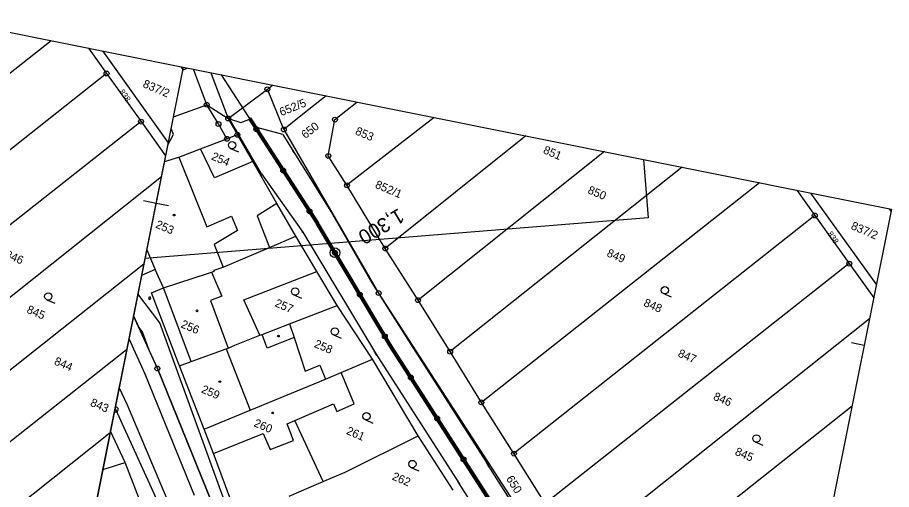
# Model space of a CAD drawing. Extents: x -548552 to -543113, y -1131925 to -1123599.
# Drawn here: x -548096.2 to -547916.5, y -1130558.1 to -1130461.1 of the extents above; entities that cross this region are included whole.
import ezdxf

# ---------------------------------------------------------------- set-up
doc = ezdxf.new("R2010")
doc.units = 0
for name, color, linetype in [('Hranice parcel', 7, 'Continuous'), ('HRANY', 7, 'Continuous'), ('NADZEMNÍ VEDENÍ VN', 7, 'Continuous'), ('Parcelní čísla', 7, 'Continuous'), ('Profile', 7, 'Continuous'), ('PROFILY NÁVRH', 7, 'Continuous'), ('STANIČENÍ', 7, 'Continuous'), ('SVAHY', 7, 'Continuous'), ('Vnitřní kresba', 7, 'Continuous'), ('Věcná břemena k části', 7, 'Continuous'), ('Značky bodu BP', 7, 'Continuous'), ('Značky budov', 7, 'Continuous'), ('Značky kultur', 7, 'Continuous')]:
    doc.layers.add(name, color=color, linetype=linetype)

msp = doc.modelspace()

# ---------------------------------------------------------------- linework, layer by layer
at = {"layer": 'Hranice parcel'}
for p, q in [((-548089.31, -1130465.88), (-548146.48, -1130511.03)), ((-548081.64, -1130467.42), (-548077.93, -1130472.61)), ((-548078.8, -1130467.99), (-548065.27, -1130486.88)), ((-548062.67, -1130471.23), (-548062.25, -1130471.81)), ((-548057.34, -1130479.04), (-548060.05, -1130471.75)), ((-548077.93, -1130472.61), (-548139.78, -1130521.55)), ((-548077.93, -1130472.61), (-548070.84, -1130482.5)), ((-548044.87, -1130475.86), (-548043.84, -1130475)), ((-548052.92, -1130481.87), (-548044.87, -1130475.86)), ((-548041.48, -1130484.13), (-548044.87, -1130475.86)), ((-548070.84, -1130482.5), (-548133.39, -1130531.79)), ((-548070.84, -1130482.5), (-548065.8, -1130489.54)), ((-548052.92, -1130481.87), (-548051.03, -1130485.23)), ((-548010.59, -1130481.67), (-548028.51, -1130495.6)), ((-548058.6, -1130488.12), (-548053.18, -1130486.05)), ((-548051.03, -1130485.23), (-548053.18, -1130486.05)), ((-548047.88, -1130490.69), (-548051.03, -1130485.23)), ((-547991.72, -1130485.45), (-548020.62, -1130508.57)), ((-547975.58, -1130488.68), (-548013.9, -1130519.21)), ((-547959.6, -1130491.88), (-548007.3, -1130529.78)), ((-548066.66, -1130493.83), (-548127.07, -1130541.87)), ((-547943.71, -1130495.07), (-548000.88, -1130540.21)), ((-548020.62, -1130508.57), (-548028.51, -1130495.6)), ((-547936.04, -1130496.61), (-547932.33, -1130501.8)), ((-547933.19, -1130497.18), (-547919.67, -1130516.07)), ((-547917.06, -1130500.41), (-547916.65, -1130500.99)), ((-547932.33, -1130501.8), (-547994.18, -1130550.73)), ((-547932.33, -1130501.8), (-547925.24, -1130511.69)), ((-548034.69, -1130513.31), (-548039.01, -1130506.06)), ((-548069.67, -1130508.83), (-548067.91, -1130512.9)), ((-548013.9, -1130519.21), (-548020.62, -1130508.57)), ((-548070.27, -1130511.83), (-548121.42, -1130552.32)), ((-548066.22, -1130516.64), (-548067.91, -1130512.9)), ((-548030.55, -1130520.28), (-548034.69, -1130513.31)), ((-547925.24, -1130511.69), (-547987.79, -1130560.98)), ((-547925.24, -1130511.69), (-547920.2, -1130518.73)), ((-548040.34, -1130524.03), (-548030.55, -1130520.28)), ((-548023.26, -1130531.32), (-548030.55, -1130520.28)), ((-548007.3, -1130529.78), (-548013.9, -1130519.21)), ((-547921.06, -1130523.02), (-547981.46, -1130571.05)), ((-548073.8, -1130529.42), (-548117.06, -1130563.53)), ((-548000.88, -1130540.21), (-548007.3, -1130529.78)), ((-548057.85, -1130545.71), (-548062.91, -1130532.7)), ((-548029.69, -1130534.09), (-548023.26, -1130531.32)), ((-548013.84, -1130547.08), (-548023.26, -1130531.32)), ((-548032.93, -1130535.41), (-548029.69, -1130534.09)), ((-547994.18, -1130550.73), (-548000.88, -1130540.21)), ((-547924.67, -1130541.01), (-547975.81, -1130581.5)), ((-548077.22, -1130546.47), (-548114.44, -1130576.02)), ((-548074.14, -1130552.54), (-548077.15, -1130546.14)), ((-548006.7, -1130558.22), (-548013.84, -1130547.08)), ((-547987.79, -1130560.98), (-547994.18, -1130550.73)), ((-548068.96, -1130565.7), (-548074.14, -1130552.54))]:
    msp.add_line(p, q, dxfattribs=at)
for points in [[(-548062.27, -1130471.9), (-548061.28, -1130471.5)], [(-548056.51, -1130472.46), (-548052.92, -1130481.87)], [(-548032.8, -1130477.21), (-548037.63, -1130481.06), (-548041.48, -1130484.13)], [(-548064.2, -1130481.54), (-548057.34, -1130479.04)], [(-548053.18, -1130486.05), (-548054.93, -1130482.99), (-548057.34, -1130479.04)], [(-548028.51, -1130495.6), (-548032.34, -1130489.56), (-548030.98, -1130482.09), (-548026.45, -1130478.49)], [(-548041.48, -1130484.13), (-548021.99, -1130517.74), (-547985.78, -1130573.7), (-547978.62, -1130586.61), (-547973.44, -1130599.62), (-547973.28, -1130611.12), (-547973.7, -1130624.88), (-547977.7, -1130646.84), (-547981.33, -1130656.63), (-547987.88, -1130668.6)], [(-548066.03, -1130490.68), (-548063.04, -1130489.81), (-548058.6, -1130488.12)], [(-548047.88, -1130490.69), (-548055.75, -1130494.06), (-548058.6, -1130488.12)], [(-548039.01, -1130506.06), (-548042.9, -1130499.31), (-548047.88, -1130490.69)], [(-548066.22, -1130516.64), (-548056.99, -1130513.63), (-548056.35, -1130513.43), (-548055.77, -1130513.24), (-548055.84, -1130513.03), (-548053.97, -1130512.43), (-548044.45, -1130508.38), (-548039.01, -1130506.06)], [(-548067.91, -1130512.9), (-548070.73, -1130514.12)], [(-548046.39, -1130526.41), (-548049.72, -1130519.13), (-548034.69, -1130513.31)], [(-548062.91, -1130532.7), (-548063.21, -1130532), (-548068.69, -1130517.71), (-548066.22, -1130516.64)], [(-548039.34, -1130606.65), (-548051.27, -1130573.08), (-548067.49, -1130533.25), (-548072.39, -1130522.4)], [(-548046.39, -1130526.41), (-548045.97, -1130526.24), (-548040.34, -1130524.03)], [(-548040.34, -1130524.03), (-548039.33, -1130526.85), (-548037.13, -1130533.79), (-548034.11, -1130532.55), (-548032.93, -1130535.41)], [(-548062.91, -1130532.7), (-548060.51, -1130531.83), (-548053.32, -1130529.22), (-548052.96, -1130529.06), (-548051.57, -1130528.46), (-548046.39, -1130526.41)], [(-548033.4, -1130556.48), (-548039.24, -1130543.9), (-548031.3, -1130540.53), (-548030.57, -1130542.11), (-548027.05, -1130540.49), (-548029.69, -1130534.09)], [(-548057.85, -1130545.71), (-548048.41, -1130541.81), (-548032.93, -1130535.41)], [(-548024.97, -1130684.14), (-548037.35, -1130647.39), (-548054.37, -1130595.1), (-548067.35, -1130560.8), (-548076.02, -1130541.68), (-548076.18, -1130541.3)], [(-548049.72, -1130563.51), (-548050.99, -1130564), (-548055.97, -1130550.71), (-548057.85, -1130545.71)], [(-548033.4, -1130556.48), (-548033.23, -1130556.41), (-548028.88, -1130554.56), (-548013.84, -1130547.08)], [(-548078.73, -1130554.02), (-548074.14, -1130552.54)], [(-548040.37, -1130559.48), (-548036.3, -1130557.72), (-548033.4, -1130556.48)]]:
    msp.add_lwpolyline(points, dxfattribs=at)
at = {"layer": 'HRANY'}
for p in [(-548050.3, -1130482.67), (-548048.34, -1130481.73)]:
    msp.add_line(p, (-548048.71, -1130482.08), dxfattribs=at)
at = {"layer": 'NADZEMNÍ VEDENÍ VN'}
for p, q in [((-548048.34, -1130481.73), (-548047.04, -1130483.74)), ((-548023.38, -1130515.61), (-548016.57, -1130526.48))]:
    msp.add_line(p, q, dxfattribs=at)
at = {"layer": 'Profile'}
for p, q in [((-548113.13, -1130461.11), (-548062.15, -1130471.33)), ((-548062.15, -1130471.33), (-548080.98, -1130565.27)), ((-547967.53, -1130490.3), (-547916.55, -1130500.51)), ((-548067.76, -1130499.31), (-548070.35, -1130498.79)), ((-548065.17, -1130499.83), (-548067.76, -1130499.31)), ((-547916.55, -1130500.51), (-547935.38, -1130594.45)), ((-548070.04, -1130510.66), (-548104.09, -1130680.55)), ((-547922.16, -1130528.49), (-547924.75, -1130527.97))]:
    msp.add_line(p, q, dxfattribs=at)
at = {"layer": 'PROFILY NÁVRH'}
for p, q in [((-548054.37, -1130472.89), (-548034.58, -1130503.42)), ((-548046.09, -1130493.23), (-548052.65, -1130481.96)), ((-548052.65, -1130481.96), (-548050.3, -1130482.67)), ((-548048.71, -1130482.08), (-548034.79, -1130503.56)), ((-548048.34, -1130481.73), (-548034.37, -1130503.29)), ((-548041.72, -1130485.17), (-548047.04, -1130483.74)), ((-548041.72, -1130485.17), (-548031.45, -1130501.55)), ((-548046.09, -1130493.23), (-548037.61, -1130505.23)), ((-548031.45, -1130501.55), (-548023.38, -1130515.61)), ((-548037.61, -1130505.23), (-548022.65, -1130530.11)), ((-548016.57, -1130526.48), (-547999.5, -1130553.08)), ((-548022.65, -1130530.11), (-548005.43, -1130556.89)), ((-547985.25, -1130575.52), (-547999.5, -1130553.08))]:
    msp.add_line(p, q, dxfattribs=at)
for points in [[(-547988.62, -1130577.15), (-548019.63, -1130528.94), (-548034.8, -1130503.55)], [(-547988.2, -1130576.88), (-548019.2, -1130528.68), (-548034.37, -1130503.29)], [(-547991.16, -1130579.07), (-548005.43, -1130556.89)]]:
    msp.add_lwpolyline(points, dxfattribs=at)
at = {"layer": 'STANIČENÍ'}
for points in [[(-548039.39, -1130488.85), (-548039.69, -1130488.43)], [(-548045.9, -1130493.49), (-548046.21, -1130493.06)], [(-548031.41, -1130501.62), (-548031.5, -1130501.46)], [(-547988.41, -1130577.01), (-548019.42, -1130528.81), (-548034.58, -1130503.42)], [(-548037.55, -1130505.32), (-548037.7, -1130505.11)], [(-548022.34, -1130530.63), (-548022.34, -1130530.62), (-548022.89, -1130529.7)], [(-547999.31, -1130553.38), (-547999.84, -1130552.56)], [(-548005.17, -1130557.3), (-548005.73, -1130556.42)]]:
    msp.add_lwpolyline(points, dxfattribs=at)
for centre, radius in [((-548048.2, -1130482.41), 0.1), ((-548047.68, -1130483.21), 0.1), ((-548047.13, -1130484.06), 0.5), ((-548047.13, -1130484.06), 0.1), ((-548046.53, -1130484.99), 0.1), ((-548045.98, -1130485.83), 0.1), ((-548045.44, -1130486.67), 0.1), ((-548044.9, -1130487.51), 0.1), ((-548044.35, -1130488.35), 0.1), ((-548043.81, -1130489.18), 0.1), ((-548043.26, -1130490.02), 0.1), ((-548042.72, -1130490.86), 0.1), ((-548042.18, -1130491.7), 0.1), ((-548041.63, -1130492.54), 0.5), ((-548041.63, -1130492.54), 0.1), ((-548041.09, -1130493.38), 0.1), ((-548040.55, -1130494.22), 0.1), ((-548040, -1130495.06), 0.1), ((-548039.46, -1130495.9), 0.1), ((-548038.91, -1130496.74), 0.1), ((-548038.37, -1130497.58), 0.1), ((-548037.83, -1130498.42), 0.1), ((-548037.28, -1130499.26), 0.1), ((-548036.74, -1130500.09), 0.1), ((-548036.2, -1130500.93), 0.5), ((-548036.2, -1130500.93), 0.1), ((-548035.65, -1130501.77), 0.1), ((-548035.11, -1130502.61), 0.1), ((-548034.56, -1130503.45), 0.1), ((-548034.05, -1130504.31), 0.1), ((-548033.54, -1130505.17), 0.1), ((-548033.03, -1130506.03), 0.1), ((-548032.51, -1130506.89), 0.1), ((-548032, -1130507.74), 0.1), ((-548032, -1130507.74), 0.1), ((-548030.97, -1130509.46), 1), ((-548031.49, -1130508.6), 0.1), ((-548031.49, -1130508.6), 0.1), ((-548030.97, -1130509.46), 0.5), ((-548030.97, -1130509.46), 0.5), ((-548030.97, -1130509.46), 0.1), ((-548030.97, -1130509.46), 0.1), ((-548030.46, -1130510.32), 0.1), ((-548030.46, -1130510.32), 0.1), ((-548029.95, -1130511.18), 0.1), ((-548029.95, -1130511.18), 0.1), ((-548029.44, -1130512.04), 0.1), ((-548029.44, -1130512.04), 0.1), ((-548028.92, -1130512.89), 0.1), ((-548028.92, -1130512.89), 0.1), ((-548028.41, -1130513.75), 0.1), ((-548027.9, -1130514.61), 0.1), ((-548027.38, -1130515.47), 0.1), ((-548026.87, -1130516.33), 0.1), ((-548026.36, -1130517.19), 0.1), ((-548025.85, -1130518.05), 0.5), ((-548025.85, -1130518.05), 0.1), ((-548025.33, -1130518.9), 0.1), ((-548024.82, -1130519.76), 0.1), ((-548024.31, -1130520.62), 0.1), ((-548023.79, -1130521.48), 0.1), ((-548023.28, -1130522.34), 0.1), ((-548022.77, -1130523.2), 0.1), ((-548022.26, -1130524.06), 0.1), ((-548021.74, -1130524.91), 0.1), ((-548021.23, -1130525.77), 0.1), ((-548020.72, -1130526.63), 0.5), ((-548020.72, -1130526.63), 0.1), ((-548020.2, -1130527.49), 0.1), ((-548019.69, -1130528.35), 0.1), ((-548019.17, -1130529.2), 0.1), ((-548018.62, -1130530.04), 0.1), ((-548018.08, -1130530.88), 0.1), ((-548017.54, -1130531.72), 0.1), ((-548017, -1130532.56), 0.1), ((-548016.46, -1130533.4), 0.1), ((-548015.92, -1130534.24), 0.1), ((-548015.38, -1130535.08), 0.5), ((-548015.38, -1130535.08), 0.1), ((-548014.84, -1130535.93), 0.1), ((-548014.3, -1130536.77), 0.1), ((-548013.76, -1130537.61), 0.1), ((-548013.21, -1130538.45), 0.1), ((-548012.67, -1130539.29), 0.1), ((-548012.13, -1130540.13), 0.1), ((-548011.59, -1130540.97), 0.1), ((-548011.05, -1130541.81), 0.1), ((-548010.51, -1130542.65), 0.1), ((-548009.97, -1130543.5), 0.5), ((-548009.97, -1130543.5), 0.1), ((-548009.43, -1130544.34), 0.1), ((-548008.89, -1130545.18), 0.1), ((-548008.35, -1130546.02), 0.1), ((-548007.81, -1130546.86), 0.1), ((-548007.26, -1130547.7), 0.1), ((-548006.72, -1130548.54), 0.1), ((-548006.18, -1130549.38), 0.1), ((-548005.64, -1130550.22), 0.1), ((-548005.1, -1130551.06), 0.1), ((-548004.56, -1130551.91), 0.5), ((-548004.56, -1130551.91), 0.1), ((-548004.02, -1130552.75), 0.1), ((-548003.48, -1130553.59), 0.1), ((-548002.94, -1130554.43), 0.1), ((-548002.4, -1130555.27), 0.1), ((-548001.85, -1130556.11), 0.1), ((-548001.31, -1130556.95), 0.1), ((-548000.77, -1130557.79), 0.1)]:
    msp.add_circle(centre, radius, dxfattribs=at)
at = {"layer": 'SVAHY'}
for p, q in [((-548062.15, -1130471.33), (-548070.04, -1130510.66)), ((-548062.15, -1130471.33), (-547967.53, -1130490.3)), ((-547967.53, -1130490.3), (-547966.56, -1130502.27)), ((-547966.56, -1130502.27), (-548070.04, -1130510.66))]:
    msp.add_line(p, q, dxfattribs=at)
at = {"layer": 'Vnitřní kresba'}
for p, q in [((-548057.34, -1130479.04), (-548052.92, -1130481.87)), ((-548063.04, -1130489.81), (-548057.32, -1130504.11)), ((-548042.9, -1130499.31), (-548046.96, -1130501.85)), ((-548057.32, -1130504.11), (-548052.23, -1130501.94)), ((-548052.23, -1130501.94), (-548051.04, -1130504.85)), ((-548046.96, -1130501.85), (-548044.45, -1130508.38)), ((-548051.04, -1130504.85), (-548055.84, -1130507.79)), ((-548055.84, -1130507.79), (-548053.97, -1130512.43)), ((-548056.35, -1130513.43), (-548054.24, -1130518.36)), ((-548060.51, -1130531.83), (-548066.22, -1130516.64)), ((-548054.24, -1130518.36), (-548056.57, -1130519.25)), ((-548056.57, -1130519.25), (-548052.96, -1130529.06)), ((-548073.33, -1130527.06), (-548070.08, -1130534.37)), ((-548044.92, -1130529.06), (-548045.97, -1130526.24)), ((-548039.33, -1130526.85), (-548044.92, -1130529.06)), ((-548053.32, -1130529.22), (-548048.41, -1130541.81)), ((-548070.08, -1130534.37), (-548059.89, -1130559.25)), ((-548075.35, -1130537.18), (-548073.72, -1130540.69)), ((-548073.72, -1130540.69), (-548065.52, -1130560.02)), ((-548040.83, -1130544.58), (-548039.24, -1130543.9)), ((-548039.52, -1130548.05), (-548040.83, -1130544.58)), ((-548055.97, -1130550.71), (-548045.76, -1130546.57)), ((-548045.76, -1130546.57), (-548044.28, -1130549.86)), ((-548044.28, -1130549.86), (-548039.52, -1130548.05))]:
    msp.add_line(p, q, dxfattribs=at)
msp.add_lwpolyline([(-548065.33, -1130487.18), (-548065.24, -1130487.15), (-548064.19, -1130485.13), (-548064.68, -1130483.91)], dxfattribs=at)
at = {"layer": 'Věcná břemena k části'}
msp.add_line((-548071.5, -1130517.93), (-548072.39, -1130522.4), dxfattribs=at)
msp.add_lwpolyline([(-548072.39, -1130522.4), (-548071.31, -1130524.8), (-548070.52, -1130525.83), (-548069.21, -1130529.43), (-548067.49, -1130533.25), (-548051.27, -1130573.08), (-548039.34, -1130606.65), (-548038.34, -1130606.19), (-548037.86, -1130605.99), (-548037.61, -1130605.87), (-548046.61, -1130579.87), (-548066.97, -1130523.89), (-548071.5, -1130517.93)], dxfattribs=at)
msp.add_lwpolyline([(-548069.33, -1130518.68), (-548069.17, -1130519.06), (-548068.81, -1130518.9), (-548068.96, -1130518.54)], close=True, dxfattribs=at)
at = {"layer": 'Značky bodu BP'}
msp.add_line((-548076.16, -1130541.2), (-548076.33, -1130542.07), dxfattribs=at)
for centre, radius in [((-548077.93, -1130472.61), 0.5), ((-548077.93, -1130472.61), 0.0303), ((-548044.87, -1130475.86), 0.5), ((-548044.87, -1130475.86), 0.0303), ((-548057.34, -1130479.04), 0.5), ((-548057.34, -1130479.04), 0.0303), ((-548070.84, -1130482.5), 0.5), ((-548070.84, -1130482.5), 0.0303), ((-548054.93, -1130482.99), 0.5), ((-548052.92, -1130481.87), 0.5), ((-548052.92, -1130481.87), 0.0303), ((-548030.98, -1130482.09), 0.5), ((-548030.98, -1130482.09), 0.0303), ((-548054.93, -1130482.99), 0.0303), ((-548041.48, -1130484.13), 0.5), ((-548041.48, -1130484.13), 0.0303), ((-548053.18, -1130486.05), 0.5), ((-548053.18, -1130486.05), 0.0303), ((-548051.03, -1130485.23), 0.5), ((-548051.03, -1130485.23), 0.0303), ((-548032.34, -1130489.56), 0.5), ((-548032.34, -1130489.56), 0.0303), ((-548028.51, -1130495.6), 0.5), ((-548028.51, -1130495.6), 0.0303), ((-547932.33, -1130501.8), 0.5), ((-547932.33, -1130501.8), 0.0303), ((-548020.62, -1130508.57), 0.5), ((-548020.62, -1130508.57), 0.0303), ((-547925.24, -1130511.69), 0.5), ((-547925.24, -1130511.69), 0.0303), ((-548021.99, -1130517.74), 0.5), ((-548021.99, -1130517.74), 0.0303), ((-548013.9, -1130519.21), 0.5), ((-548013.9, -1130519.21), 0.0303), ((-548007.3, -1130529.78), 0.5), ((-548007.3, -1130529.78), 0.0303), ((-548067.49, -1130533.25), 0.5), ((-548067.49, -1130533.25), 0.0303), ((-548000.88, -1130540.21), 0.5), ((-548000.88, -1130540.21), 0.0303), ((-548076.02, -1130541.68), 0.0303), ((-547994.18, -1130550.73), 0.5), ((-547994.18, -1130550.73), 0.0303)]:
    msp.add_circle(centre, radius, dxfattribs=at)
msp.add_arc((-548076.02, -1130541.68), 0.5, 230.727, 106.6037, dxfattribs=at)
at = {"layer": 'Značky budov'}
for centre in [(-548064.05, -1130501.72), (-548059.35, -1130521.39), (-548042.59, -1130526.59), (-548054.64, -1130535.95), (-548043.78, -1130542.37)]:
    msp.add_circle(centre, 0.175, dxfattribs=at)
at = {"layer": 'Značky kultur'}
for p, q in [((-548052.43, -1130488.04), (-548050.82, -1130488.73)), ((-548039.44, -1130518.12), (-548037.84, -1130518.81)), ((-547963.45, -1130517.85), (-547961.84, -1130518.54)), ((-548090.21, -1130519.11), (-548088.6, -1130519.8)), ((-548031.29, -1130526.34), (-548029.69, -1130527.03)), ((-548024.79, -1130543.75), (-548023.18, -1130544.44)), ((-547944.61, -1130548.3), (-547943, -1130548.99)), ((-548015.36, -1130553.56), (-548013.75, -1130554.25))]:
    msp.add_line(p, q, dxfattribs=at)
for centre in [(-548052.13, -1130487.35), (-548039.15, -1130517.43), (-547963.15, -1130517.16), (-548089.91, -1130518.42), (-548031, -1130525.65), (-548024.49, -1130543.06), (-547944.31, -1130547.61), (-548015.06, -1130552.87)]:
    msp.add_circle(centre, 0.75, dxfattribs=at)

# ---------------------------------------------------------------- texts
at = {"layer": 'Parcelní čísla'}
for s, height, rotation, p in [('837/2', 1.7, 336.8058, (-548070.63, -1130475.35)), ('838', 1.2, 304.8058, (-548075.4, -1130476.37)), ('652/5', 1.7, 21.8058, (-548041.99, -1130481.41)), ('650', 1.7, 37.8058, (-548037.08, -1130486.11)), ('853', 1.7, 336.8058, (-548026.94, -1130485.06)), ('851', 1.7, 336.8058, (-547988.31, -1130488.94)), ('254', 1.7, 336.8058, (-548056.53, -1130490.24)), ('852/1', 1.7, 336.8058, (-548022.87, -1130496.05)), ('850', 1.7, 336.8058, (-547979.15, -1130497.17)), ('253', 1.7, 336.8058, (-548068, -1130504.23)), ('837/2', 1.7, 336.8058, (-547925.03, -1130504.53)), ('838', 1.2, 304.8058, (-547929.8, -1130505.56)), ('846', 1.7, 336.8058, (-548098.94, -1130510.4)), ('849', 1.7, 336.8058, (-547975.24, -1130510.11)), ('845', 1.7, 336.8058, (-548094.49, -1130521.73)), ('257', 1.7, 336.8058, (-548043.47, -1130520.41)), ('848', 1.7, 336.8058, (-547967.66, -1130520.33)), ('256', 1.7, 336.8058, (-548062.8, -1130524.73)), ('258', 1.7, 336.8058, (-548035.39, -1130528.78)), ('847', 1.7, 336.8058, (-547960.6, -1130530.73)), ('844', 1.7, 336.8058, (-548088.85, -1130532.35)), ('259', 1.7, 336.8058, (-548058.6, -1130538.12)), ('846', 1.7, 336.8058, (-547953.33, -1130539.59)), ('843', 1.7, 336.8058, (-548081.42, -1130540.85)), ('260', 1.7, 336.8058, (-548047.79, -1130545.06)), ('261', 1.7, 336.8058, (-548028.79, -1130546.65)), ('845', 1.7, 336.8058, (-547948.88, -1130550.92)), ('262', 1.7, 336.8058, (-548019.37, -1130556.01)), ('650', 1.7, 301.8058, (-547995.85, -1130555.88))]:
    msp.add_text(s, height=height, rotation=rotation, dxfattribs=at).set_placement(p)
at = {"layer": 'STANIČENÍ'}
msp.add_text('1,300', height=3, rotation=210.8551, dxfattribs=at).set_placement((-548017.88, -1130500.21))

doc.saveas('drawing.dxf')
